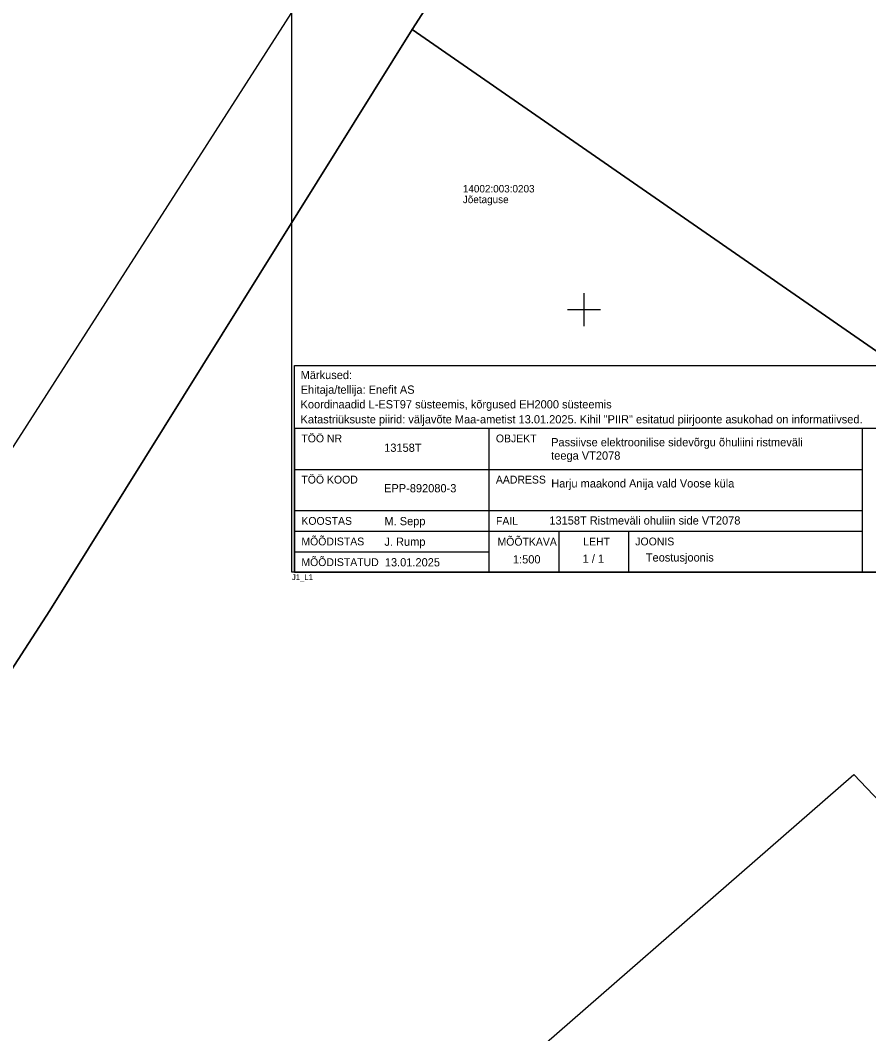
# Model space of a CAD drawing. Extents: x 579747 to 582499, y 6562295 to 6565613.
# Drawn here: x 581981.6 to 582084.6, y 6564512.1 to 6564635.1 of the extents above; entities that cross this region are included whole.
import ezdxf

# ---------------------------------------------------------------- set-up
doc = ezdxf.new("R2010")
doc.units = 0
for name, color, linetype in [('PIIR', 7, 'Continuous'), ('VORK', 7, 'Continuous'), ('VORMISTUS', 7, 'Continuous')]:
    doc.layers.add(name, color=color, linetype=linetype)

msp = doc.modelspace()

# ---------------------------------------------------------------- linework, layer by layer
at = {"layer": 'PIIR'}
for points in [[(582135.55, 6564808.67), (582068.96, 6564721.02), (582017.54, 6564640.84), (581956.73, 6564546.01), (581888.98, 6564444.16), (581819.5, 6564352.29), (581772.04, 6564298.67), (581650.74, 6564171.18), (581565.74, 6564073.89), (581521.68, 6564027.95), (581462.2, 6563979.51), (581405.77, 6563949.46), (581387.54, 6563937.32), (581346.36, 6563914.86)], [(581384.59, 6563917.2), (581404.32, 6563931.05), (581456.61, 6563960.43), (581471.37, 6563968.93), (581531.08, 6564017.57), (581575.85, 6564064.19), (581579.4, 6564062.41), (581615.32, 6564103.23), (581653.52, 6564150.59), (581684.72, 6564185.3), (581762.65, 6564266.98), (581831.7, 6564341.91), (581902.22, 6564435.18), (581985.17, 6564563.48), (582029.16, 6564634.01), (582078.75, 6564711.15), (582146.74, 6564800.25)], [(582014.75, 6564335.19), (582035.66, 6564380.18), (582103.73, 6564436.23), (582089.97, 6564448.66), (582033.11, 6564500.24), (582082.76, 6564543.57), (582125.31, 6564498.78), (582136.01, 6564487.52), (582199.06, 6564516.3), (582192.43, 6564520.86), (582029.16, 6564634.01), (581985.17, 6564563.48), (581902.22, 6564435.18), (581831.7, 6564341.91)]]:
    msp.add_lwpolyline(points, dxfattribs=at)
msp.add_lwpolyline([(582078.75, 6564711.15), (582029.16, 6564634.01), (582192.43, 6564520.86), (582199.06, 6564516.3), (582287.58, 6564527.55), (582301.82, 6564540.75), (582292.62, 6564547.98)], close=True, dxfattribs=at)
at = {"layer": 'VORK'}
for p, q in [((582050, 6564602), (582050, 6564598)), ((582048, 6564600), (582052, 6564600))]:
    msp.add_line(p, q, dxfattribs=at)
at = {"layer": 'VORMISTUS'}
for p, q in [((582014.86, 6564585.61), (582107.05, 6564585.61)), ((582014.86, 6564585.61), (582014.86, 6564568.11)), ((582038.48, 6564568.11), (582038.48, 6564585.61)), ((582083.82, 6564568.11), (582083.82, 6564585.61)), ((582014.86, 6564580.6), (582083.82, 6564580.6)), ((582014.86, 6564575.6), (582083.82, 6564575.6)), ((582014.86, 6564573.09), (582083.82, 6564573.09)), ((582046.93, 6564573.1), (582046.93, 6564568.11)), ((582055.39, 6564573.1), (582055.39, 6564568.11)), ((582014.86, 6564570.59), (582038.48, 6564570.59)), ((582014.87, 6564568.11), (582107.05, 6564568.11))]:
    msp.add_line(p, q, dxfattribs=at)
for points in [[(582014.55, 6564568.11), (582014.55, 6564711.11), (582107.05, 6564711.11), (582107.05, 6564568.11)], [(582107.05, 6564568.11), (582014.86, 6564568.11), (582014.86, 6564593.2), (582107.05, 6564593.2)]]:
    msp.add_lwpolyline(points, close=True, dxfattribs=at)
msp.add_lwpolyline([(582014.86, 6564568.11), (582107.05, 6564568.11)], dxfattribs=at)

# ---------------------------------------------------------------- texts
at = {"layer": 'PIIR'}
for s, p in [('14002:003:0203', (582035.3, 6564614.22)), ('Jõetaguse', (582035.3, 6564612.92))]:
    msp.add_text(s, height=0.9, dxfattribs=at).set_placement(p)
at = {"layer": 'VORMISTUS'}
for s, height, p in [('Märkused:', 1, (582015.61, 6564591.56)), ('Ehitaja/tellija: Enefit AS', 1, (582015.61, 6564589.78)), ('Koordinaadid L-EST97 süsteemis, kõrgused EH2000 süsteemis', 1, (582015.6, 6564588)), ('Katastriüksuste piirid: väljavõte Maa-ametist 13.01.2025. Kihil "PIIR" esitatud piirjoonte asukohad on informatiivsed.', 1, (582015.6, 6564586.18)), ('TÖÖ NR', 0.95, (582015.7, 6564583.88)), ('13158T', 1, (582025.75, 6564582.73)), ('OBJEKT', 0.95, (582039.31, 6564583.88)), ('Passiivse elektroonilise sidevõrgu õhuliini ristmeväli', 1, (582046.02, 6564583.4)), ('teega VT2078', 1, (582046.02, 6564581.78)), ('TÖÖ KOOD', 0.95, (582015.7, 6564578.88)), ('EPP-892080-3', 1, (582025.74, 6564577.81)), ('AADRESS', 0.95, (582039.31, 6564578.88)), ('Harju maakond Anija vald Voose küla', 1, (582046.03, 6564578.4)), ('KOOSTAS', 0.95, (582015.7, 6564573.87)), ('M. Sepp', 1, (582025.78, 6564573.82)), ('FAIL', 0.95, (582039.32, 6564573.87)), ('13158T Ristmeväli ohuliin side VT2078', 1, (582045.8, 6564573.9)), ('MÕÕDISTAS', 0.95, (582015.7, 6564571.37)), ('J. Rump', 1, (582025.78, 6564571.32)), ('MÕÕTKAVA', 0.95, (582039.51, 6564571.34)), ('LEHT', 0.95, (582049.91, 6564571.36)), ('JOONIS', 0.95, (582056.23, 6564571.37)), ('1 / 1', 1, (582049.84, 6564569.26)), ('Teostusjoonis', 1, (582057.51, 6564569.41)), ('MÕÕDISTATUD', 0.95, (582015.7, 6564568.86)), ('13.01.2025', 1, (582025.83, 6564568.82)), ('1:500', 1, (582041.38, 6564569.18)), ('J1_L1', 0.7, (582014.55, 6564567.16))]:
    msp.add_text(s, height=height, dxfattribs=at).set_placement(p)

doc.saveas('drawing.dxf')
